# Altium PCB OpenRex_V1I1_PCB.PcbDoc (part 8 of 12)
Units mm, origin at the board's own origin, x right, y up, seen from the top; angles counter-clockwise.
Board outline 70 x 95 mm, 10 copper layers (L1, L2, L3, L4 (PWR), L5 (PWR), L6 (PWR), L7 (PWR), L8, L9, L10), stack 1.632 mm thick; 1080 components, 708 nets, 3831 pads, 2373 vias.
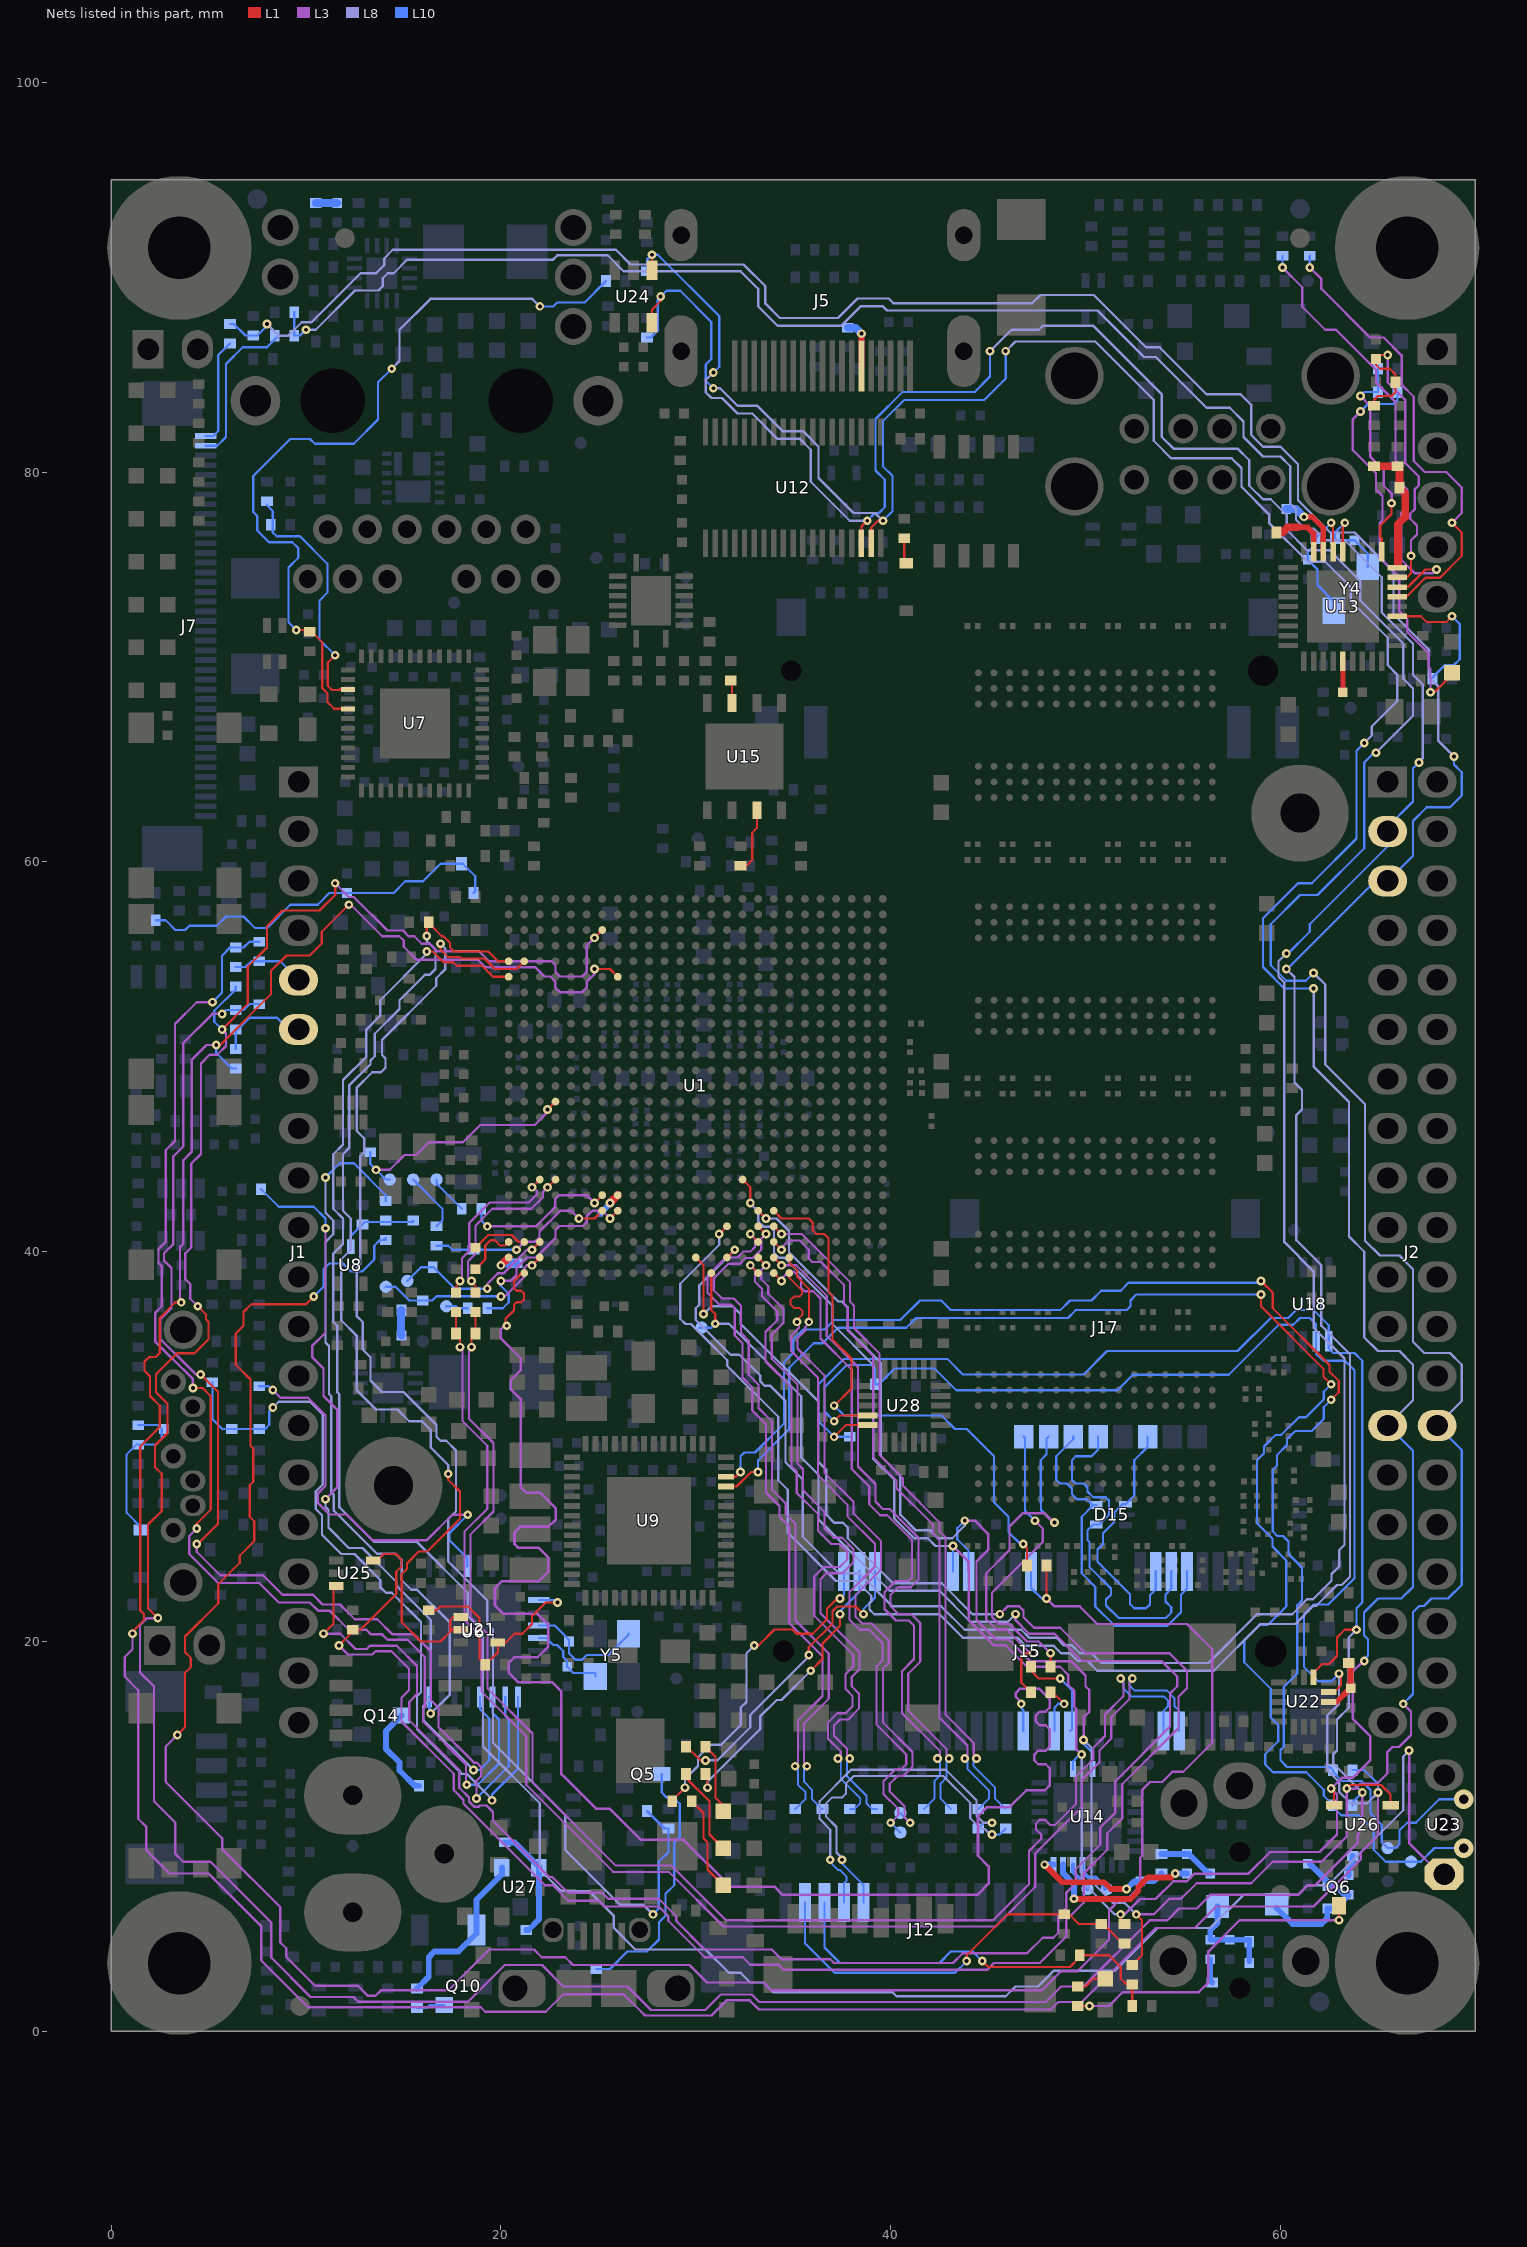
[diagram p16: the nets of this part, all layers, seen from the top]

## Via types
v1: diameter 0.45, hole 0.2, L1 to L10, tented both sides, 2369 vias
v2: diameter 1, hole 0.5, L1 to L10, tented top, 4 vias

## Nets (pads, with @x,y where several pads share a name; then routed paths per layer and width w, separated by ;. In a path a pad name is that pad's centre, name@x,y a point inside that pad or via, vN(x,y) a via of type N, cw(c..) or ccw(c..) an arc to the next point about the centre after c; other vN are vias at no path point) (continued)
HP_OUT_L: C285.1 C289.1 C290.2 FB22.1 R231.2 | length 5
  L10 w0.3: C290.2@56.775,6.4 56.775,5.575 56.4,5.2 C285.1@56.4,4.7 C289.1@57.4,4.7 58.4,4.7 FB22.1@58.4,3.6
HP_OUT_R: C284.1 C288.1 C291.2 FB21.1 R230.2 | length 7.7
  L10 w0.3: C291.2@59.8,6.325 60.625,5.5 62.1,5.5 62.4,5.8 C288.1@62.4,6.3 62.8,6.3 C284.1@63.5,7 63.3,7 62.8,7.5 62.5,7.5 62.5,7.6 FB21.1@61.5,8.6
HUB_CFG_SEL0: R221.2 U13.24 | length 24.3
  L1 w0.114: U13.24@66,73.6 66.462,73.6 67.442,74.58 68.18,74.58 69.3,75.7 69.3,76.9 v1(68.8,77.4)
  L3 w0.12: v1(61.5,90.5) 62.1,89.9 62.1,89.4 64.6,86.9 65.3,86.9 66.215,85.985 66.215,84.485 66.84,83.86 66.84,80.56 67.4,80 68.5,80 69.3,79.2 69.3,77.9 v1(68.8,77.4)
  L10 w0.114: v1(61.5,90.5) R221.2@61.5,91.1
HUB_CFG_SEL1: R220.2 U13.25 | length 23.2
  L1 w0.114: U13.25@66,74.1 66.544,74.1 67.444,75 v1(68,75)
  L3 w0.12: v1(60.1,90.5) 61.115,89.485 61.115,88.485 62.3,87.3 62.844,87.3 64.9,85.244 64.9,84.6 65.9,83.6 65.9,80.6 66.1,80.4 66.1,79.5 66.5,79.1 66.5,78.2 66.2,77.9 66.2,75.5 66.9,74.8 67.8,74.8 v1(68,75)
  L10 w0.114: v1(60.1,90.5) R220.2@60.1,91.1
HUB_CRFILT: C254.1 U13.14 | length 1.6
  L1 w0.25: C254.1@63.2,68.7 U13.14@63.2,70.3
HUB_LED: D12.2 R219.1 | length 20.4
  L1 w0.114: v1(67.7,68.7) 67.9,68.7 68.8,69.6 D12.2@68.8,69.7
  L3 w0.12: v1(64.1,83.1) 63.715,82.715 63.715,81.12 64.9,79.935 64.9,79.1 65.235,78.765 65.235,77.535 65.1,77.4 65.1,75.6 66.1,74.6 66.1,72.86 66.5,72.46 66.5,71.8 67.6,70.7 67.6,70 67.7,69.9 v1(67.7,68.7)
  L10 w0.114: v1(64.1,83.1) 64.485,83.485 65.785,83.485 66,83.7 R219.1@66,84.1
HUB_NON_REM1: R224.2 U13.22 | length 7.3
  L1 w0.114: U13.22@66,72.6 67.2,72.6 67.5,72.3 68.5,72.3 v1(68.8,72.6)
  L10 w0.114: R224.2@67.8,69.4 67.8,69.456 68.444,70.1 68.9,70.1 69.2,70.4 69.2,72.2 v1(68.8,72.6)
HUB_PLLFILT: C253.1 U13.34 | length 3.5
  L1 w0.28: v1(61.2,77.7) 61.635,77.7 62.2,77.135 U13.34@62.2,75.9
  L10 w0.4: C253.1@60.3,78.1 60.8,78.1 v1(61.2,77.7)
HUB_RBIAS: R222.1 U13.35 | length 3.1
  L1 w0.28: 60.9,77.165 61.393,77.165 61.7,76.858 U13.35@61.7,75.9
  L1 w0.4: R222.1@59.8,76.9 60.1,76.9 60.365,77.165 60.9,77.165
HUB_RESETN: C416.1 R217.1 R218.1 U13.26 | length 17.8
  L1 w0.114: R217.1@64.8,83.4 64.8,83.7 65,83.9 65.7,83.9 65.9,84.1 R218.1@65.9,84.6 65.9,85 65.6,85.3 65.1,85.3 64.9,85.5 C416.1@64.9,85.8 65.1,86 v1(65.5,86) ; U13.26@66,74.6 66.5,74.6 66.7,74.8 v1(66.7,75.7)
  L3 w0.12: v1(65.5,86) 65.5,84.6 66.4,83.7 66.4,80.459 67.1,79.759 67.1,79.318 66.88,79.098 66.88,78.08 66.656,77.856 66.656,77.6 67,77.256 67,76.8 66.7,76.5 v1(66.7,75.7)
HUB_VBUS_DET: R169.1 R215.2 R216.1 U13.27 | length 6.7
  L1 w0.28: U13.27@66,75.1 U13.27@66,75.175
  L1 w0.4: R169.1@64.8,80.3 R215.2@66,80.3 66.1,80.2 R216.1@66.1,79.2 66.4,78.9 66.4,77.7 66.025,77.325 U13.27@66.025,75.175
HUB_XTALIN: C415.1 R358.2 U13.33 Y4.3 | length 7.1
  L1 w0.114: v1(62.6,77.4) 62.7,77.3 U13.33@62.7,75.9
  L10 w0.114: v1(62.6,77.4) R358.2@61.8,76.6 61.8,76.3 61.4,75.9 C415.1@61.4,75.5 61.9,75 61.9,74.2 62.725,73.375 Y4.3@62.725,72.875
HUB_XTALOUT: C242.1 R358.1 U13.32 Y4.1 | length 5.2
  L1 w0.114: U13.32@63.2,75.9 63.2,77.3 v1(63.3,77.4)
  L10 w0.114: v1(63.3,77.4) 62.8,76.9 R358.1@62.8,76.6 62.9,76.5 C242.1@63.8,76.5 64.475,75.825 Y4.1@64.475,75.125
I2C1_SCL: R132.1 R238.1 R278.1 U1.H20 U18.6 U22.4 U28.11 | length 218
  L1 w0.114: v1(1.1,20.4) 1.1,20.5 1.685,21.085 1.685,21.409 1.5,21.594 1.5,30 2.5,31 2.5,32.1 2,32.6 2,33.6 1.715,33.885 1.715,34.359 1.956,34.6 2.3,34.6 2.5,34.8 2.5,36.6 3.3,37.4 v1(3.6,37.4) ; v1(5.4,50.6) 5.6,50.6 8.2,53.2 8.2,54.4 9,55.2 10.2,55.2 10.815,55.815 10.815,56.415 v1(12.2,57.8) ; v1(24.8,54.5) 25.6,54.5 U1.H20@26,54.1 ; v1(37.1,31.3) 37.4,31.6 U28.11@38.825,31.6 ; U22.4@62.475,17.4 62.751,17.4 63.1,17.749 63.1,18.25 v1(63,18.35)
  L3 w0.12: v1(1.1,20.4) 1.1,19.6 0.7,19.2 0.7,18.2 1.4,17.5 1.4,10.9 1.8,10.5 1.8,9.3 3,8.1 5,8.1 7.7,5.4 7.7,3.644 10.109,1.235 18.965,1.235 19.2,1 22.3,1 23.2,1.9 26.3,1.9 27.2,1 27.39,0.81 30.8,0.81 31.575,1.585 32.775,1.585 33.245,1.115 48.215,1.115 48.6,1.5 49.8,1.5 53.6,5.3 55.6,5.3 56.7,6.4 61.7,6.4 64.115,8.815 64.115,9.171 65,10.056 v1(65,12.25) ; v1(3.6,37.4) 3.535,37.465 3.535,40.235 3.7,40.4 3.7,44.684 4.135,45.119 4.135,49.835 4.9,50.6 v1(5.4,50.6) ; v1(12.2,57.8) 12.3,57.8 13.915,56.185 14.789,56.185 15.015,55.959 15.015,55.641 15.671,54.985 18.815,54.985 19.2,54.6 21.756,54.6 22.241,54.115 22.529,54.115 22.785,53.859 22.785,53.571 23.041,53.315 24.159,53.315 24.415,53.571 24.415,53.859 24.8,54.244 v1(24.8,54.5)
  L8 w0.12: v1(63,18.35) 63,16.8 62.4,16.2 62.4,13.4 63.015,12.785 63.015,12.285 63.6,11.7 64.45,11.7 v1(65,12.25)
  L10 w0.114: v1(5.4,50.6) 5.4,50.2 6.2,49.4 R278.1@6.4,49.4 ; v1(37.1,31.3) 36.6,31.8 36.6,33.044 37.741,34.185 39.015,34.185 39.2,34 R132.1@39.2,33.2 39.4,33.2 40.2,34 42.256,34 43.371,32.885 51.635,32.885 52.435,33.685 57.341,33.685 59.906,36.25 60.65,36.25 61,36.6 61.5,36.6 61.825,36.275 U18.6@61.825,35.4 61.825,34.775 62.2,34.4 63.315,34.4 63.8,33.915 63.8,23.244 62.456,21.9 61.7,21.9 61.2,21.4 61.2,18.7 61.935,17.965 62.615,17.965 v1(63,18.35) ; R238.1@63.7,13.4 64.3,13.4 65,12.7 v1(65,12.25)
I2C1_SCL_CON: J1.6 R278.2 R279.2 | length 4.7
  L10 w0.114: R278.2@6.4,50.4 R279.2@6.4,51.4 6.5,51.4 7.1,52 8.52,52 9.12,51.4 J1.6@9.62,51.4
I2C1_SCL_MCU: R279.1 R291.1 U6.10 | length 62.3
  L1 w0.114: v1(4.4,25) 4.444,25 5.485,26.041 5.485,32.815 v1(4.6,33.7)
  L3 w0.12: v1(4.4,25) 4.4,24.6 5.6,23.4 7.8,23.4 8.8,22.4 10.356,22.4 10.856,21.9 11.74,21.9 12.5,21.14 13.66,21.14 14.435,20.365 15.535,20.365 16.415,19.485 16.415,16.985 16.8,16.6 16.8,15.6 18.615,13.785 18.759,13.785 18.985,13.559 18.985,13.085 18.75,12.85 v1(18.75,11.95) ; v1(4.6,33.7) 4.361,33.7 3.231,34.83 3.22,34.83 2.54,35.51 2.54,36.54 3.1,37.1 3.1,39.156 2.715,39.541 2.715,39.915 3.2,40.4 3.2,44.9 3.7,45.4 3.7,50.7 5.2,52.2 v1(5.7,52.2)
  L10 w0.114: v1(5.7,52.2) 5.9,52.4 R279.1@6.4,52.4 6.8,52.4 7.1,52.7 R291.1@7.6,52.7 ; v1(18.75,11.95) 20.4,13.6 20.4,16 20.225,16.175 U6.10@20.225,17.15
I2C1_SCL_PMIC: R238.2 TP18.1 U9.54 | length 78.2
  L1 w0.114: U9.54@31.55,28.45 32.05,28.45 v1(32.3,28.7) ; v1(59,38.5) 59.6,37.9 59.6,37.1 62.515,34.185 62.515,33.841 62.985,33.371 62.985,32.785 v1(62.6,32.4)
  L1 w0.4: v2@69.35,11.95 v2(69.4,11.9)
  L10 w0.114: v1(32.3,28.7) 32.3,29.5 32.5,29.7 33.044,29.7 34.52,31.176 34.52,34.32 35,34.8 35,35.5 35.5,36 36.6,36 37.1,36.5 40.5,36.5 41.5,37.5 42.6,37.5 43.1,37 48.7,37 49.2,37.5 50.3,37.5 50.8,38 51.8,38 52.2,38.4 58.9,38.4 v1(59,38.5) ; v1(62.6,32.4) 62.215,32.015 62.215,31.415 61.6,30.8 60.756,30.8 60.335,30.38 60.335,30.08 59.815,29.559 59.815,29.241 59.815,29.015 59.598,28.798 59.598,25.658 59.841,25.415 60.129,25.415 60.415,25.129 60.415,24.485 61.1,23.8 61.1,22.1 60.86,21.86 60.86,18.36 60.165,17.665 60.165,14.6 60,14.435 60,13.9 60.335,13.565 62.535,13.565 R238.2@62.7,13.4 62.7,13.3 63.165,12.835 64.165,12.835 64.615,12.385 64.615,11.185 65.2,10.6 65.2,9.7 TP18.1@65.5,9.4 65.9,9.4 66.1,9.6 66.1,10.3 66.5,10.7 66.942,10.7 68.142,11.9 v2(69.4,11.9)
I2C1_SDA: R28.1 R247.1 R276.1 U1.G23 U18.5 U22.6 U28.12 | length 218.7
  L1 w0.114: v1(2.4,21.2) 1.9,21.7 1.9,26 2.6,26.7 2.6,28.6 2.258,28.942 2.258,30.058 2.9,30.7 2.9,32.2 2.3,32.8 2.3,33.7 3.385,34.785 4.285,34.785 5,35.5 5,36.406 4.865,36.541 4.865,36.785 v1(4.45,37.2) ; v1(5.7,51.4) 7.015,52.715 7.015,54.615 8,55.6 8,56.7 8.8,57.5 10.7,57.5 11.5,58.3 v1(11.5,58.9) ; v1(24.8,56.1) U1.G23@25.2,56.5 ; v1(37.1,30.5) 37.7,31.1 U28.12@38.825,31.1 ; U22.6@61.7,18.175 61.7,18.4 62.144,18.844 62.494,18.844 62.9,19.25 62.9,20.2 63.3,20.6 v1(63.9,20.6)
  L3 w0.12: v1(2.4,21.2) 1.844,21.2 1.485,20.841 1.485,18.415 2.2,17.7 2.2,11.8 3.3,10.7 3.3,9.1 3.7,8.7 5.1,8.7 8.215,5.585 8.215,3.781 10.24,1.756 12.444,1.756 12.685,1.515 18.315,1.515 20.2,3.4 22.104,3.4 23.204,2.3 26.5,2.3 27.71,1.09 30.49,1.09 31.285,1.885 32.871,1.885 33.256,1.5 47.956,1.5 48.756,2.3 49.9,2.3 53.3,5.7 54.2,5.7 54.8,6.3 55.7,6.3 56.4,7 60.9,7 61.4,7.5 61.8,7.5 63.956,9.656 63.956,10.1 64.2,10.344 v1(64.2,12.25) ; v1(4.45,37.2) 4.065,37.585 4.065,38.335 3.815,38.585 3.815,39.915 4.12,40.22 4.12,44.52 4.615,45.015 4.615,49.659 5.056,50.1 5.444,50.1 5.9,50.556 5.9,51.2 v1(5.7,51.4) ; v1(11.5,58.9) 12.2,58.2 12.456,58.2 14.181,56.475 14.975,56.475 15.265,56.185 15.559,56.185 15.944,55.8 16.344,55.8 16.729,55.415 18.885,55.415 19.4,54.9 22.6,54.9 22.8,54.7 22.8,54.356 23.041,54.115 24.159,54.115 24.4,54.356 24.4,55.7 v1(24.8,56.1)
  L8 w0.12: v1(63.9,20.6) 63.5,20.2 63.5,16.6 62.9,16 62.9,14.4 62.7,14.2 62.7,13.75 v1(64.2,12.25)
  L10 w0.114: v1(5.7,51.4) 5.3,51.8 5.3,52.356 6.4,53.456 R276.1@6.4,53.6 ; R28.1@37.9,30.5 v1(37.1,30.5) 36.3,31.3 36.3,33.2 37.6,34.5 42.9,34.5 43.7,33.7 49.9,33.7 51.1,34.9 57.8,34.9 59.5,36.6 60.4,36.6 60.8,37 61.7,37 62.475,36.225 U18.5@62.475,35.4 62.475,35.025 62.7,34.8 63.8,34.8 64.2,34.4 64.2,22 63.9,21.7 v1(63.9,20.6) ; R247.1@63.7,11.6 63.7,11.75 v1(64.2,12.25)
I2C1_SDA_CON: J1.5 R276.2 R277.2 | length 3.8
  L10 w0.114: R276.2@6.4,54.6 6.9,54.6 7.2,54.9 R277.2@7.6,54.9 8.68,54.9 9.62,53.96 J1.5@9.62,53.94
I2C1_SDA_MCU: R277.1 R290.1 U6.11 | length 64.5
  L1 w0.114: v1(4.2,33) 4.7,33 5.12,32.58 5.12,26.764 4.4,26.044 v1(4.4,25.8)
  L3 w0.12: v1(4.2,33) 4.2,33.466 3.116,34.55 3.104,34.55 2.26,35.394 2.26,36.86 2.6,37.2 2.6,39.26 2.435,39.425 2.435,40.135 2.8,40.5 2.8,45.2 3.285,45.685 3.285,51.685 4.4,52.8 v1(5.2,52.8) ; v1(4.4,25.8) 4.015,25.415 4.015,24.485 5.5,23 7.6,23 8.6,22 10.2,22 10.615,21.585 11.215,21.585 12.2,20.6 13.106,20.6 13.341,20.365 13.907,20.365 14.187,20.085 15.215,20.085 16.1,19.2 16.1,16.629 16.015,16.544 16.015,15.885 18.215,13.685 18.215,12.685 v1(18.25,12.65) ; v1@18.3,12.7 v1@18.4,12.6
  L10 w0.114: v1(5.2,52.8) 5.7,53.3 5.7,55.2 6.1,55.6 R290.1@6.4,55.6 6.8,55.6 7.1,55.9 R277.1@7.6,55.9 ; v1(18.25,12.65) 18.815,12.65 19.9,13.735 19.9,16 19.575,16.325 U6.11@19.575,17.15
I2C1_SDA_PMIC: R247.2 TP21.1 U9.53 | length 77.7
  L1 w0.114: U9.53@31.55,27.95 32.094,27.95 32.844,28.7 v1(33.2,28.7) ; v1(59,37.8) 59,37.2 62.2,34 62.2,33.6 v1(62.6,33.2)
  L1 w0.4: v2@69.35,9.45 v2@69.4,9.4
  L10 w0.114: v1(33.2,28.7) 33.2,29.3 34.8,30.9 34.8,34.044 36.056,35.3 36.5,35.3 37.3,36.1 40.8,36.1 41.3,36.6 49.1,36.6 49.5,37 52.1,37 52.3,37.2 52.3,37.5 52.6,37.8 v1(59,37.8) ; v1(62.6,33.2) 62.215,32.815 62.215,32.411 61.304,31.5 60.944,31.5 60.044,30.6 59.756,30.6 59.157,30.002 59.157,29.657 58.8,29.3 58.8,26.06 59.585,25.275 59.585,24.871 60.3,24.156 60.3,21.8 59.36,20.86 58.937,20.86 58.14,20.063 58.14,18.937 59.5,17.577 59.5,16.1 59.885,15.715 59.885,14.885 59.215,14.215 59.215,13.685 59.615,13.285 61.321,13.285 62.215,12.391 62.215,12.085 R247.2@62.7,11.6 62.7,11.5 63.115,11.085 64.015,11.085 64.785,10.315 64.785,9.315 65.4,8.7 TP21.1@66.7,8.7 67.2,8.7 67.9,9.4 v2@69.4,9.4
  other v2: 69.4,9.39
I2C2_CSI_SCL: J12.13 R53.1 R154.2 R191.2 | length 21.4
  L1 w0.114: v1(44.7,3.6) 45,3.3 49.2,3.3 49.7,3.8 R53.1@49.7,3.9 51.2,3.9 51.8,3.3 51.8,2.7 52.1,2.4 R154.2@52.4,2.4 R191.2@52.4,1.3
  L10 w0.114: J12.13@36.6,6.6 36.6,4.3 37.4,3.5 42.5,3.5 43.1,4.1 44.2,4.1 v1(44.7,3.6)
I2C2_CSI_SDA: J12.14 R52.1 R54.2 R156.2 | length 21.1
  L1 w0.114: v1(43.9,3.6) 43.9,3.9 46,6 R52.1@48.9,6 49.156,6 49.656,5.5 R54.2@50.8,5.5 50.9,5.5 51.9,4.5 R156.2@52,4.5
  L10 w0.114: J12.14@35.6,6.6 35.6,4.52 37.12,3 43.3,3 v1(43.9,3.6)
I2C2_SCL: J2.28 J15.30 R134.1 R154.1 U1.U5 U12.17 U14.29 U24.1 U26.6 | length 220
  L1 w0.114: U24.1@27.75,90.45 v1(27.75,91.15) ; U1.U5@33.2,42.1 v1(33.6,41.7) ; U12.17@38.5,76.35 38.5,77.2 v1(38.8,77.5) ; R154.1@52.4,3.4 52.9,3.9 52.9,5.7 v1(52.6,6) ; v1(63.4,12.45) 63.585,12.635 65.159,12.635 65.65,12.144 U26.6@65.65,11.6
  L3 w0.12: v1(43.8,26.2) 44.319,26.2 45,25.519 45,24.7 44.4,24.1 44.4,21.1 45.4,20.1 46.056,20.1 47.176,18.98 49.275,18.98 50,18.255 50,17.7 50.185,17.515 50.185,16.385 49.9,16.1 v1(49.9,14.95) ; v1(52.6,6) 53.5,6 54.3,6.8 54.9,6.8 55.7,7.6 58.5,7.6 59.6,8.7 62.1,8.7 63.4,10 v1(63.4,12.45) 63.85,12.45 64.1,12.7 64.944,12.7 65.485,13.241 65.485,14.329 65.741,14.585 66.085,14.585 66.7,15.2 66.7,16.4 v1(66.3,16.8)
  L8 w0.12: v1(30.9,85.1) 30.515,84.715 30.515,84.085 30.8,83.8 31.344,83.8 32.144,83 32.9,83 34.2,81.7 35.344,81.7 35.9,81.144 35.9,79.5 37.9,77.5 v1(38.8,77.5) ; v1(33.6,41.7) 34.144,41.7 34.785,41.059 34.785,39.971 37.311,37.444 37.5,37.444 37.8,37.144 37.8,36 39.5,34.3 39.5,29.5 40.5,28.5 40.5,26.5 41.3,25.7 42.025,25.7 42.425,25.3 43.156,25.3 43.8,25.944 v1(43.8,26.2) ; v1(45.1,86.2) 46.2,87.3 47.6,87.3 47.8,87.5 50.4,87.5 53.9,84 53.9,81.81 54.51,81.2 57.8,81.2 58.4,80.6 58.4,79.3 59.1,78.6 59.5,78.6 60.32,77.78 60.32,77.036 61.366,75.99 62.51,75.99 64.1,74.4 64.1,73.4 66.3,71.2 66.3,69.4 66.8,68.9 66.8,67.5 v1(64.9,65.6) ; v1(49.9,14.95) 50.3,14.55 50.3,7.7 51.4,6.6 52,6.6 v1(52.6,6) ; v1(61.7,54.3) 62.3,53.7 62.3,49.6 64.34,47.56 64.34,40.56 65.1,39.8 66.1,39.8 66.8,39.1 66.8,35.38 67.38,34.8 68.7,34.8 69.3,34.2 69.3,32.34 J2.28@68.04,31.08
  L10 w0.114: R134.1@27.5,90.3 27.5,90.9 v1(27.75,91.15) 28.05,91.15 31.2,88 31.2,85.4 v1(30.9,85.1) ; v1(38.8,77.5) 39.2,77.9 39.4,77.9 39.7,78.2 39.7,79.6 39.22,80.08 39.22,82.72 40.6,84.1 44.3,84.1 45.1,84.9 v1(45.1,86.2) ; v1(43.8,26.2) 43.412,25.813 43.412,25.243 44,24.656 J15.30@44,23.6 ; v1(49.9,14.95) 49.9,14.744 50.33,14.314 50.33,13.47 U14.29@50.35,13.45 ; v1(61.7,54.3) 61.3,53.9 60.3,53.9 59.5,54.7 59.5,56.8 61,58.3 61.9,58.3 64.3,60.7 64.3,65.1 64.8,65.6 v1(64.9,65.6) ; v1(66.3,16.8) 66.8,17.3 66.8,21.5 67.115,21.815 67.359,21.815 67.744,22.2 68.6,22.2 69.3,22.9 69.3,29.82 J2.28@68.04,31.08
I2C2_SDA: J2.27 J15.32 R133.1 R156.1 U1.T7 U12.18 U14.27 U24.6 U26.1 | length 208.2
  L1 w0.114: U24.6@27.75,87.65 27.75,88.331 28.2,88.781 v1(28.2,89) ; U1.T7@32.4,43.7 32.8,43.3 v1(32.8,42.5) ; U12.18@39,76.35 39,77.156 39.344,77.5 v1(39.6,77.5) ; v1(51.8,6) 51.8,5.7 R156.1@52,5.5 ; v1(62.6,12.45) 62.75,12.3 U26.1@62.75,11.6
  L3 w0.12: v1(43.2,24.9) 44,24.1 44,21.1 45.3,19.8 45.9,19.8 47,18.7 48.7,18.7 49.115,18.285 49.115,17.785 49.415,17.485 49.415,16.641 49.515,16.541 49.515,14.485 v1(49.8,14.2) ; v1(51.8,6) 52,6 52.785,6.785 53.589,6.785 54.504,7.7 55.2,7.7 55.59,8.09 58.36,8.09 59.47,9.2 62,9.2 62.9,10.1 62.9,12.15 v1(62.6,12.45) 63.15,13 63.7,13 64.6,13.9 64.6,15.144 63.7,16.044 63.7,18.444 ; v1(64.3,19) 64.256,19 63.7,18.444 ; v1@64.3,19.05 63.7,18.45 63.7,18.444
  L8 w0.12: v1(30.9,84.3) 31.244,84.3 32.149,83.395 33.161,83.395 34.456,82.1 35.5,82.1 36.3,81.3 36.3,79.7 38.1,77.9 39.2,77.9 v1(39.6,77.5) ; v1(32.8,42.5) 32.8,42.47 33.2,42.07 33.2,41.556 33.471,41.285 33.815,41.285 34.015,41.085 34.015,39.941 34.271,39.685 34.559,39.685 37,37.244 37,36.3 39.1,34.2 39.1,29.392 40.185,28.307 40.185,26.315 41.2,25.3 41.9,25.3 42.3,24.9 v1(43.2,24.9) ; v1(45.9,86.2) 46.4,86.7 50.5,86.7 53.5,83.7 53.5,81.6 54.4,80.7 57.5,80.7 58,80.2 58,79.24 59.415,77.825 59.415,77.391 61.406,75.4 62.3,75.4 63.6,74.1 63.6,73.4 65.5,71.5 65.5,70.1 65.985,69.615 65.985,68.241 64.685,66.941 64.685,66.485 v1(64.3,66.1) ; v1(49.8,14.2) 49.8,7.7 51.5,6 v1(51.8,6) ; v1(61.7,53.5) 61.7,49.5 63.515,47.685 63.515,40.785 64.3,40 64.3,35.6 65,34.9 66.1,34.9 66.8,34.2 66.8,32.38 J2.27@65.5,31.08
  L10 w0.114: R133.1@27.5,86.9 27.7,86.9 28.05,87.25 28.05,88.85 v1(28.2,89) 28.5,89.3 29.2,89.3 30.8,87.7 30.8,85.8 30.515,85.515 30.515,84.685 v1(30.9,84.3) ; v1(39.6,77.5) 40.1,78 40.1,79.8 39.6,80.3 39.6,82.6 40.7,83.7 44.8,83.7 45.9,84.8 v1(45.9,86.2) ; J15.32@43.2,23.6 v1(43.2,24.9) ; U14.27@49.35,13.45 49.35,13.85 49.7,14.2 v1(49.8,14.2) ; v1(61.7,53.5) 60.2,53.5 59.1,54.6 59.1,57.1 60.9,58.9 61.6,58.9 63.9,61.2 63.9,65.7 v1(64.3,66.1) ; v1@64.3,19.1 64.485,19.285 64.485,20.115 64.285,20.315 64.285,21.485 65,22.2 66.2,22.2 66.8,22.8 66.8,29.78 J2.27@65.5,31.08
I2C3_CSI1_SCL: J7.40 R196.1 | length 5.5
  L10 w0.114: J7.40@4.85,81.85 5.25,81.85 5.5,82.1 5.5,86 R196.1@6.1,86.6
I2C3_CSI1_SDA: J7.39 R195.1 | length 8.1
  L10 w0.114: J7.39@4.85,81.35 5.45,81.35 5.9,81.8 5.9,85.544 6.756,86.4 8,86.4 R195.1@8.5,86.9
I2C3_SCL: J2.5 R142.1 R196.2 U1.R4 | length 186
  L1 w0.114: v1(31.2,40.9) U1.R4@31.6,41.3
  L8 w0.12: v1(8,87.6) 8.6,87 9.1,87 9.785,87.685 10.285,87.685 12.8,90.2 13.6,90.2 14.015,90.615 14.015,90.959 14.455,91.399 25.906,91.399 26.656,90.65 32.45,90.65 33.571,89.529 33.571,88.641 34.311,87.9 37.3,87.9 38.3,88.9 39.9,88.9 40.135,88.665 47.265,88.665 47.685,89.085 50.415,89.085 53.1,86.4 53.8,86.4 56.215,83.985 57.959,83.985 58.5,83.444 58.5,81.9 59.1,81.3 60,81.3 60.9,80.4 60.9,78.556 62.556,76.9 63.8,76.9 65.8,74.9 65.8,72.7 67.615,70.885 67.615,69.485 68.1,69 68.1,66.2 v1(68.9,65.4) ; v1(31.2,40.9) 31.2,40.356 29.2,38.356 29.2,36.556 29.471,36.285 29.759,36.285 30.6,35.444 31.615,34.429 31.615,34.141 34.23,31.526 34.23,28.27 34.715,27.785 34.715,25.585 37.2,23.1 38.244,23.1 39,22.344 39,22.056 38.915,21.971 38.915,21.641 39.156,21.4 42.5,21.4 43.7,20.2 46.5,20.2 46.915,19.785 47.2,19.785 48.359,19.785 48.744,19.4 49.2,19.4 49.6,19 50.1,19 50.6,18.5 56.577,18.5 58.977,20.9 60.764,20.9 61.7,21.836 61.836,21.836 62.9,22.9 63.144,22.9 63.565,23.321 63.565,34.735 62.1,36.2 62.1,39.3 60.815,40.585 60.815,47.015 61.1,47.3 61.1,48.3 60.715,48.685 60.715,54.085 v1(60.3,54.5)
  L10 w0.114: R196.2@6.1,87.6 6.3,87.6 6.9,87 R142.1@7.3,87 7.5,87 8,87.5 v1(8,87.6) ; v1(60.3,54.5) 60.344,54.5 64.864,59.02 J2.5@65.5,59.02 66.8,60.32 66.8,62.1 67.5,62.8 68.7,62.8 69.3,63.4 69.3,64.6 68.9,65 v1(68.9,65.4)
I2C3_SDA: J2.3 R137.1 R195.2 U1.R2 | length 176.6
  L1 w0.114: U1.R2@31.6,39.7 v1(32,40.1)
  L8 w0.12: v1(10,87.3) 10.5,87.3 12.515,89.315 13.715,89.315 13.941,89.541 13.941,89.941 14.2,90.2 14.5,90.2 15.2,90.9 22.681,90.9 22.9,91.119 25.481,91.119 26.3,90.3 32.3,90.3 33.2,89.4 33.2,88.504 34.204,87.5 37.456,87.5 38.456,88.5 39.6,88.5 39.815,88.285 50.615,88.285 53,85.9 53.6,85.9 56.2,83.3 57.4,83.3 58.1,82.6 58.1,81.8 59.1,80.8 60,80.8 60.5,80.3 60.5,78.4 60.8,78.1 60.8,77.556 61.271,77.085 61.715,77.085 62.3,76.5 63.3,76.5 65.2,74.6 65.2,72.79 66.8,71.19 66.8,69.6 67.3,69.1 67.3,65.3 v1(67.1,65.1) ; v1(32,40.1) 32,40.09 30.185,38.275 30.185,37.285 30,37.1 30,36.5 31.785,34.715 32.229,34.715 33.315,33.629 33.315,33.341 33.541,33.115 33.829,33.115 34.6,32.344 34.6,29.2 35.485,28.315 35.485,25.371 37.356,23.5 38.4,23.5 40.1,21.8 42.6,21.8 43.8,20.6 46.7,20.6 47.1,20.2 48.5,20.2 48.9,19.8 49.3,19.8 49.7,19.4 50.3,19.4 50.8,18.9 56.3,18.9 58.8,21.4 60.6,21.4 61.366,22.166 61.666,22.166 62.615,23.115 62.615,23.459 63.01,23.854 63.01,24.69 63.285,24.965 63.285,34.515 61.7,36.1 61.7,38.989 60.2,40.489 60.2,53.8 59.9,54.1 59.9,54.9 v1(60.3,55.3)
  L10 w0.114: R137.1@9.4,88.2 R195.2@9.4,87 9.7,87 v1(10,87.3) ; v1(60.3,55.3) 60.385,55.3 61.5,56.415 61.5,56.8 65.5,60.8 J2.3@65.5,61.56 65.5,61.8 66.8,63.1 66.8,64.8 v1(67.1,65.1)
IR_RCV: U1.A20 U23.1 | length 121.6
  L1 w0.114: v1(16.2,55.4) 16.5,55.4 17.055,54.845 17.555,54.845 17.732,54.668 19.032,54.668 19.6,54.1 U1.A20@20.4,54.1
  L3 w0.12: v1(66.6,14.4) 66.6,9.656 68.196,8.06 U23.1@68.4,8.06
  L8 w0.12: v1(16.2,55.4) 16.2,55.29 13.81,52.9 13.81,52.11 13.1,51.4 13.1,50.004 11.9,48.804 11.9,45.5 11.4,45 11.4,42.2 11.9,41.7 11.9,40.4 11.4,39.9 11.4,36.4 11.6,36.2 11.6,32.8 11.715,32.685 11.715,26.885 13.5,25.1 15.7,25.1 18.3,22.5 18.3,21.3 19.085,20.515 19.085,14.615 22,11.7 22,8.3 23.1,7.2 24.519,7.2 25.8,5.919 25.8,5.3 26.9,4.2 30.5,4.2 31.7,3 32.3,3 32.8,2.5 33.475,2.5 33.975,2 40.1,2 40.3,1.8 45.9,1.8 46.4,2.3 47.56,2.3 48.36,3.1 51.5,3.1 53.7,5.3 56.4,5.3 58.1,7 60.9,7 61.4,7.5 62.456,7.5 66.3,11.344 66.3,14.1 v1(66.6,14.4)
JTAG_MOD: R61.2 U1.H6 | length 1.3
  L1 w0.4: v1(25.6,42.5) U1.H6@26,42.9
  L10 w0.3: R61.2@25.1,41.965 25.6,42.465 v1(25.6,42.5)
JTAG_NTRST: R62.1 TP1.1 U1.C2 | length 9.4
  L1 w0.114: v1(21.6,39.3) U1.C2@22,39.7
  L3 w0.12: v1(20,37.7) 20.2,37.7 21.2,38.7 21.2,39.164 21.336,39.3 v1(21.6,39.3)
  L10 w0.114: TP1.1@14.1,38.2 14.6,38.2 15.3,37.5 R62.1@16,37.5 16.485,37.5 16.7,37.715 19.985,37.715 v1(20,37.7)
JTAG_TCK: R92.2 TP12.1 | length 1.1
  L10 w0.114: TP12.1@17.2,37.2 17.7,37.2 17.8,37.1 R92.2@18.3,37.1
JTAG_TCK_R: R92.1 U1.H5 | length 10.9
  L1 w0.114: v1(25.6,41.7) U1.H5@26,42.1
  L3 w0.12: v1(20,38.5) 20.5,38.5 20.8,38.8 20.8,39.16 21.34,39.7 21.8,39.7 22.8,40.7 22.8,41.1 23.015,41.315 24.2,41.315 24.4,41.515 24.4,41.8 24.7,42.1 25.2,42.1 v1(25.6,41.7)
  L10 w0.114: R92.1@19.3,37.1 20.1,37.1 20.4,37.4 20.4,37.844 20,38.244 v1(20,38.5)
JTAG_TDI: R90.2 TP2.1 | length 3.1
  L10 w0.114: TP2.1@15.5,43.7 17,42.2 17,41.6 R90.2@16.7,41.3
JTAG_TDI_R: R63.1 R90.1 U1.G5 | length 9.9
  L1 w0.114: v1(24,41.7) 24.8,41.7 U1.G5@25.2,42.1
  L3 w0.12: v1(20.8,40.1) 21.215,40.515 21.759,40.515 21.985,40.741 21.985,41.029 23.056,42.1 23.6,42.1 v1(24,41.7)
  L10 w0.114: R90.1@16.7,40.3 17.3,40.3 17.5,40.1 R63.1@18.6,40.1 v1(20.8,40.1)
JTAG_TDO: R161.2 TP13.1 | length 2
  L10 w0.114: TP13.1@16.7,43.7 16.7,43.5 17,43.2 R161.2@18,42.2
JTAG_TDO_R: R161.1 U1.G6 | length 8.2
  L1 w0.114: v1(24.8,42.5) U1.G6@25.2,42.9
  L3 w0.12: v1(19.3,41.3) 21.8,41.3 22.5,42 22.785,42.285 22.785,42.685 23,42.9 24.4,42.9 v1(24.8,42.5)
  L10 w0.114: R161.1@19,42.2 19,41.6 v1(19.3,41.3)
JTAG_TMS: R64.1 TP5.1 U1.C3 | length 8.7
  L1 w0.114: v1(21.6,40.1) U1.C3@22,40.5
  L3 w0.12: v1(19.3,38.1) 19.3,38.344 19.841,38.885 20.129,38.885 20.959,39.715 21.344,40.1 v1(21.6,40.1)
  L10 w0.114: TP5.1@15.2,38.5 15.9,39.2 R64.1@16.5,39.2 16.544,39.2 17.644,38.1 v1(19.3,38.1)
LED1: R82.1 R94.1 U7.17 | length 40.7
  L1 w0.114: v1(9.5,71.9) 10.1,71.9 R94.1@10.2,71.8 10.3,71.8 10.835,71.265 10.835,68.925 11.1,68.66 11.1,68.2 11.45,67.85 U7.17@12.16,67.85
  L8 w0.12: v1(14.4,85.3) 14.8,85.7 14.8,87.3 16.385,88.885 21.615,88.885 v1(22,88.5)
  L10 w0.114: v1(9.5,71.9) 9.1,72.3 9.1,75.1 9.6,75.6 9.6,76.1 9.3,76.4 8.1,76.4 7.5,77 7.5,77.744 7.3,77.944 7.3,79.8 9.2,81.7 10.206,81.7 10.459,81.447 12.447,81.447 13.7,82.7 13.7,84.6 v1(14.4,85.3) ; v1(22,88.5) 22.7,88.5 22.9,88.7 24.3,88.7 R82.1@25.4,89.8
LED2: R81.1 R102.2 U7.15 | length 13.1
  L1 w0.114: v1(11.5,70.6) 11.115,70.215 11.115,69.041 11.341,68.815 11.7,68.815 11.735,68.85 U7.15@12.16,68.85
  L10 w0.114: R81.1@8,78.3 8.3,78 8.3,76.9 8.5,76.7 9.7,76.7 11.1,75.3 11.1,73.8 10.7,73.4 10.7,71.4 v1(11.5,70.6)
LED_MPCIE_WLAN: J15.44 R268.1 | length 15.2
  L1 w0.114: R268.1@30.5,13.2 30.6,13.1 v1(30.6,12.5) ; v1(35.9,18.5) 36.5,19.1 36.5,19.9 37.4,20.8 v1(37.4,21.4)
  L8 w0.12: v1(30.6,12.5) 30.6,12.8 33.3,15.5 33.3,16.144 34.156,17 34.4,17 v1(35.9,18.5)
  L10 w0.114: v1(37.4,21.4) 37.4,21.544 38.4,22.544 J15.44@38.4,23.6
LED_MPCIE_WPAN: J15.46 R269.1 | length 17.4
  L1 w0.114: R269.1@28.8,11.8 28.8,11.85 v1(29.45,12.5) ; v1(33,19.8) 33.23,19.8 34.04,20.61 34.96,20.61 35.17,20.4 36,20.4 36.735,21.135 36.735,21.675 37.26,22.2 v1(37.4,22.2)
  L8 w0.12: v1(29.45,12.5) 29.45,12.95 30.115,13.615 30.115,14.059 30.756,14.7 31.3,14.7 32.3,15.7 32.3,16.6 32.6,16.9 32.6,19.4 v1(33,19.8)
  L10 w0.114: v1(37.4,22.2) 37.6,22.4 J15.46@37.6,23.6
LED_MPCIE_WWAN: J15.42 R267.1 | length 16.3
  L1 w0.114: R267.1@29.5,14.6 29.544,14.6 30.244,13.9 v1(30.5,13.9) ; v1(35.8,19.3) 35.8,19.7 37.015,20.915 37.015,21.559 37.256,21.8 38.2,21.8 v1(38.6,21.4)
  L8 w0.12: v1(30.5,13.9) 31.1,13.9 32.8,15.6 32.8,16.23 35.8,19.23 v1(35.8,19.3)
  L10 w0.114: v1(38.6,21.4) 38.6,21.656 39.2,22.256 J15.42@39.2,23.6
"LOCAL_PWR / NON_REM0": R219.2 R223.2 U13.28 | length 11.1
  L1 w0.114: U13.28@65.2,75.9 65.2,76.6 65.115,76.685 65.115,77.259 65.7,77.844 v1(65.7,78.4)
  L3 w0.12: v1(64.1,83.9) 64.6,83.4 64.6,80.8 65.3,80.1 65.3,79.3 65.7,78.9 v1(65.7,78.4)
  L10 w0.114: v1(64.1,83.9) 64.3,84.1 R219.2@65,84.1 R223.2@65,85.3
LVDS0_CLK_N: R135.1 U1.V4 | length 35.6
  L1 w0.1: U1.V4@34,41.3 v1(34.4,40.9)
  L3 w0.11: v1(34.4,40.9) 35.453,40.9 37.92,38.433 37.92,37.433 38.12,37.233 38.12,36.08 39.42,34.78 39.42,29.58 40.62,28.38 40.62,28 42.5,26.12 42.5,25.663 42.82,25.343 42.82,16.233 44.26,14.793 44.26,14.14 v1(44.4,14)
  L10 w0.1: v1(44.4,14) 44.26,13.86 44.26,13.6 45.36,12.5 45.36,11.94 R135.1@45.9,11.4
LVDS0_CLK_P: R138.1 U1.V3 | length 35.6
  L1 w0.1: U1.V3@34,40.5 v1(34.4,40.1)
  L3 w0.11: v1(34.4,40.1) 34.4,40.207 34.773,40.58 35.32,40.58 35.8,40.1 35.8,39.65 35.978,39.472 36.428,39.472 37.6,38.3 37.6,37.3 37.8,37.1 37.8,35.947 39.1,34.647 39.1,29.447 40.3,28.247 40.3,27.867 42.18,25.987 42.18,25.53 42.5,25.21 42.5,16.1 43.94,14.66 43.94,14.14 v1(43.8,14)
  L10 w0.1: v1(43.8,14) 43.94,13.86 43.94,13.467 45.04,12.367 45.04,11.94 R138.1@44.5,11.4
LVDS0_CLK_R_N: J12.11 R129.2 R135.2 | length 17.8
  L8 w0.11: v1(37.5,8.8) 37.5,8.893 37.22,9.173 37.22,10.48 36.675,11.025 36.675,11.675 37,12 37.515,12 37.7,12.185 37.7,12.7 38.1,13.1 42.7,13.1 44.08,11.72 44.08,10.927 44.627,10.38 44.827,10.38 45.107,10.1 v1(45.2,10.1)
  L10 w0.1: v1(37.5,8.8) 37.5,8.623 38.6,7.523 J12.11@38.6,6.6 ; v1(45.2,10.1) 45.6,10.1 R135.2@45.9,10.4
LVDS0_CLK_R_P: J12.12 R136.2 R138.2 | length 17.8
  L8 w0.11: v1(36.9,8.8) 36.9,10.347 36.355,10.892 36.355,11.808 37.967,13.42 42.833,13.42 44.4,11.853 44.4,11.06 44.76,10.7 v1(45.2,10.7)
  L10 w0.1: v1(36.9,8.8) 36.9,8.672 37.287,8.285 37.386,8.285 37.735,7.936 37.735,7.735 37.6,7.6 J12.12@37.6,6.6 ; R138.2@44.5,10.4 44.8,10.7 v1(45.2,10.7)
LVDS0_TX0_N: R65.1 U1.U2 | length 35.5
  L1 w0.1: U1.U2@33.2,39.7 v1(33.6,39.3)
  L3 w0.11: v1(33.6,39.3) 33.36,39.06 33.36,38.593 33.72,38.233 33.72,37.843 34.5,37.063 34.5,36.347 33.9,35.747 33.9,34.5 35.226,33.174 35.226,29.126 35.5,28.853 35.5,27.753 36.6,26.653 36.6,25.8 37.08,25.32 37.508,25.32 38.095,24.733 38.095,24.067 37.528,23.5 36.7,23.5 36.4,23.2 36.4,21.453 38.4,19.453 38.4,18.58 38,18.18 38,17.7 38.37,17.33 38.37,16.554 37.816,16 37.4,16 37.1,15.7 37.1,15.153 37.76,14.493 37.76,14.14 v1(37.9,14)
  L10 w0.1: v1(37.9,14) 37.76,13.86 37.76,13.093 38.76,12.093 38.76,11.7 39.06,11.4 R65.1@39.3,11.4
LVDS0_TX0_P: R119.1 U1.U1 | length 35.5
  L1 w0.1: v1(32.8,39.3) U1.U1@33.2,38.9
  L3 w0.11: v1(32.8,39.3) 33.04,39.06 33.04,38.46 33.4,38.1 33.4,37.71 34.18,36.93 34.18,36.48 33.58,35.88 33.58,34.367 34.906,33.041 34.906,28.994 35.18,28.72 35.18,27.62 36.28,26.52 36.28,25.667 36.947,25 37.375,25 37.775,24.6 37.775,24.2 37.395,23.82 36.567,23.82 36.08,23.333 36.08,21.32 38.08,19.32 38.08,18.713 37.68,18.313 37.68,17.567 38.05,17.197 38.05,16.687 37.683,16.32 37.267,16.32 36.78,15.833 36.78,15.02 37.44,14.36 37.44,14.14 v1(37.3,14)
  L10 w0.1: v1(37.3,14) 37.44,13.86 37.44,12.96 38.44,11.96 38.44,11.7 38.14,11.4 R119.1@37.9,11.4
LVDS0_TX1_N: R121.1 U1.U4 | length 35.6
  L1 w0.1: U1.U4@33.2,41.3 v1(33.6,40.9)
  L3 w0.11: v1(33.6,40.9) 33.36,40.66 33.36,40.107 32.933,39.68 32.57,39.68 32.27,39.38 31.68,39.38 30.925,38.625 30.925,38.028 31.353,37.6 31.953,37.6 32.32,37.233 32.32,35.833 32.72,35.433 32.72,33.68 33.22,33.18 33.22,31.98 33.92,31.28 33.92,27.78 34.62,27.08 34.62,26.533 35.12,26.033 35.12,21.08 36.82,19.38 36.82,17.067 35.56,15.807 35.56,13.74 v1(35.7,13.6)
  L10 w0.1: v1(35.7,13.6) 35.56,13.46 35.56,12.793 35.96,12.393 35.96,11.94 R121.1@36.5,11.4
LVDS0_TX1_P: R123.1 U1.U3 | length 35.6
  L1 w0.1: v1(32.8,40.9) U1.U3@33.2,40.5
  L3 w0.11: v1(32.8,40.9) 33.04,40.66 33.04,40.24 32.8,40 32.437,40 32.137,39.7 31.547,39.7 30.605,38.758 30.605,37.895 31.22,37.28 31.82,37.28 32,37.1 32,35.7 32.4,35.3 32.4,33.547 32.9,33.047 32.9,31.847 33.6,31.147 33.6,27.647 34.3,26.947 34.3,26.4 34.8,25.9 34.8,20.947 36.5,19.247 36.5,17.2 35.24,15.94 35.24,13.74 v1(35.1,13.6)
  L10 w0.1: R123.1@35.1,11.4 35.64,11.94 35.64,12.26 35.24,12.66 35.24,13.46 v1(35.1,13.6)
LVDS0_TX2_N: R126.1 U1.V2 | length 35.5
  L1 w0.1: U1.V2@34,39.7 v1(34.4,39.3)
  L3 w0.11: v1(34.4,39.3) 35.153,39.3 36.72,37.733 36.72,35.68 38.32,34.08 38.32,28.98 39.22,28.08 39.22,27.18 39.6,26.8 39.953,26.8 41.42,25.333 41.42,23.167 41.033,22.78 40.38,22.78 40,22.4 40,21.803 40.403,21.4 41.065,21.4 41.52,20.945 41.52,18.967 40.9,18.347 40.9,16.453 42.86,14.493 42.86,14.14 v1(43,14)
  L10 w0.1: v1(43,14) 42.86,13.86 42.86,13.007 42.56,12.707 42.56,11.94 R126.1@43.1,11.4
LVDS0_TX2_P: R128.1 U1.V1 | length 35.5
  L1 w0.1: U1.V1@34,38.9 v1(34.4,38.5)
  L3 w0.11: v1(34.4,38.5) 34.4,38.607 34.773,38.98 35.02,38.98 35.4,38.6 35.4,38.15 35.578,37.972 36.028,37.972 36.4,37.6 36.4,35.547 38,33.947 38,28.847 38.9,27.947 38.9,27.047 39.467,26.48 39.82,26.48 41.1,25.2 41.1,23.3 40.9,23.1 40.247,23.1 39.68,22.533 39.68,21.67 40.27,21.08 40.933,21.08 41.2,20.813 41.2,19.1 40.58,18.48 40.58,16.32 42.54,14.36 42.54,14.14 v1(42.4,14)
  L10 w0.1: R128.1@41.7,11.4 42.24,11.94 42.24,12.84 42.54,13.14 42.54,13.86 v1(42.4,14)
LVDS0_TX3_N: TP19.1 U1.W2 | length 35.5
  L1 w0.1: U1.W2@34.8,39.7 34.8,39.444 35.2,39.044 35.2,38.709 35.8,38.109 v1(35.8,36.4)
  L3 w0.11: v1(35.8,36.4) 35.8,36.307 35.62,36.127 35.62,35.957 35.22,35.557 35.22,35.033 36.6,33.653 36.6,28.653 38.1,27.153 38.1,26.553 39.512,25.141 39.512,23.712 38.2,22.4 38.2,21.263 38.543,20.92 39.033,20.92 39.9,20.053 39.9,18.9 39.6,18.6 39.6,15.853 41.12,14.333 41.12,13.567 40.653,13.1 40.353,13.1 39.95,12.697 39.95,12.303 40.71,11.543 40.71,10.99 v1(41,10.7)
  L10 w0.1: TP19.1@40.5,11.2 v1(41,10.7)
LVDS0_TX3_P: TP20.1 U1.W1 | length 35.5
  L1 w0.1: U1.W1@34.8,38.9 34.8,38.657 35.46,37.997 35.46,37.83 35.33,37.7 35.058,37.7 34.858,37.5 34.858,37.3 35.058,37.1 35.33,37.1 35.48,36.95 35.48,36.78 35.2,36.5 v1(35.2,36.4)
  L3 w0.11: v1(35.2,36.4) 35.3,36.3 35.3,36.09 34.9,35.69 34.9,34.9 36.28,33.52 36.28,28.52 37.78,27.02 37.78,26.42 39.192,25.008 39.192,23.845 37.88,22.533 37.88,21.13 38.41,20.6 38.9,20.6 39.58,19.92 39.58,19.033 39.28,18.733 39.28,15.72 40.8,14.2 40.8,13.7 40.52,13.42 40.22,13.42 39.63,12.83 39.63,12.17 40.39,11.41 40.39,11.09 v1(40,10.7)
  L10 w0.1: v1(40,10.7) TP20.1@40.5,10.2
MCU_BTN: C314.1 D35.1 R149.1 R390.2 | length 19.7
  L10 w0.114: R390.2@2.3,57 2.8,57 3.3,56.5 3.8,56.5 4.02,56.72 5.42,56.72 5.9,57.2 6.8,57.2 7.4,56.6 8,56.6 9.2,57.8 10.6,57.8 11.2,58.4 C314.1@12.1,58.4 14.5,58.4 15.1,59 16,59 16.9,59.9 D35.1@17.981,59.9 18.044,59.9 18.685,59.259 18.685,58.485 R149.1@18.6,58.4
MCU_GPIO0: R227.1 U6.12 | length 41.6
  L3 w0.12: v1(11,27.3) 11.6,27.9 11.6,31.9 10.9,32.6 10.9,34.012 10.315,34.597 10.315,35.159 11,35.844 v1(11,41.2)
  L8 w0.12: v1(11,27.3) 11,26.9 11.155,26.745 11.155,25.845 12.2,24.8 12.894,24.8 14.635,23.059 14.635,22.865 16.4,21.1 16.4,17.075 16.015,16.69 16.015,15.985 v1(18.6,13.4)
  L10 w0.114: R227.1@7.7,43.2 8.6,42.3 10.4,42.3 11,41.7 v1(11,41.2) ; v1(18.6,13.4) 18.9,13.4 19.4,13.9 19.4,16.044 18.925,16.519 U6.12@18.925,17.15
MCU_GPIO1: R228.1 U6.28 | length 21.2
  L3 w0.12: v1(8.3,32.9) 8.7,32.5 10.1,32.5 11,31.6 11,27.985 10.615,27.6 10.615,27.1 11.199,26.516 12.084,26.516 13.4,25.2 16.21,25.2 17.51,26.5 v1(18.3,26.5) ; v1@18.25,26.55 v1@18.3,26.6
  L10 w0.114: R228.1@7.6,33.1 8,33.1 8.1,33.1 v1(8.3,32.9) ; U6.28@18.275,23.85 18.275,24.281 17.365,25.191 17.365,25.559 17.415,25.609 17.415,25.615 v1(18.3,26.5)
MCU_GPIO2: R148.1 R205.2 R273.1 U6.9 | length 39.5
  L8 w0.12: v1(8.3,32) 8.6,32.3 10.2,32.3 10.86,31.64 10.86,28.06 10.5,27.7 10.5,26.8 10.82,26.48 10.82,25.48 11.815,24.485 12.484,24.485 13.806,23.163 13.806,22.8 14.106,22.5 14.4,22.5 15.9,21 15.9,17.4 15.7,17.2 15.7,15.5 18,13.2 18.256,13.2 v1@19.55,11.906 ; v1(19.55,11.85) v1@19.55,11.906 ; v1@19.6,11.856 v1@19.55,11.906
  L10 w0.114: R148.1@5.2,33.3 5.2,31.4 5.7,30.9 R205.2@6.2,30.9 R273.1@7.6,30.9 7.9,30.9 8.12,31.12 8.12,31.82 v1(8.3,32) ; v1(19.55,11.85) 19.55,12.15 20.875,13.475 U6.9@20.875,17.15
MCU_ISPN: R204.2 R213.1 U1.B21 | length 72.1
  L1 w0.114: v1(16.9,55.8) 16.9,55.5 17.275,55.125 17.875,55.125 17.963,55.037 19.163,55.037 19.7,54.5 20.8,54.5 U1.B21@21.2,54.9
  L8 w0.12: v1(16.9,55.8) 17.156,55.544 17.156,54.5 16.685,54.029 16.685,53.641 13.9,50.856 13.9,50.1 14.085,49.915 14.085,49.441 13.844,49.2 13.4,49.2 12.6,48.4 12.6,46.204 12.985,45.819 12.985,45.1 12.785,44.9 12.785,39.341 12.6,39.156 12.6,36.7 12.915,36.385 12.915,34.985 13.315,34.585 13.315,33.385 13.9,32.8 15,32.8 16.7,31.1 16.7,30.5 16.9,30.3 17.2,30.3 17.7,29.8 17.7,26.685 17.3,26.285 17.3,24.1 18.8,22.6 19.3,22.1 19.3,20.9 19.6,20.6 19.6,14.8 23.3,11.1 23.3,9.3 26.1,6.5 27.3,6.5 v1(27.8,6)
  L10 w0.114: R213.1@27.5,11.3 28.4,10.4 R204.2@28.6,10.4 28.6,9.2 28.1,8.7 28.1,6.3 v1(27.8,6)
MCU_RSTINN: R212.1 U1.A21 U21.1 U21.2 | length 54.2
  L1 w0.114: v1(16.2,56.2) 16.2,56.7 16.4,56.9 16.4,56.756 16.971,56.185 17.059,56.185 17.385,55.859 17.385,55.615 17.595,55.405 19.351,55.405 19.841,54.915 ; v1(17.3,28.6) 17.3,28.3 17.9,27.7 17.9,26.3 16.22,24.62 15.794,24.62 15.18,24.006 15.18,23.724 14.915,23.459 14.915,20.985 15.9,20 16.9,20 17.4,20.5 ; U21.2@17.95,20.6 17.5,20.6 17.4,20.5 ; U21.1@17.95,21.25 17.55,21.25 17.4,21.1 17.4,20.5 ; 19.841,54.915 19.856,54.9 U1.A21@20.4,54.9 20.4,54.915 19.841,54.915
  L8 w0.12: v1(16.2,56.2) 16.2,55.944 16.644,55.5 16.644,54.5 16.344,54.2 16.1,54.2 14.8,52.9 14.8,52.456 13.525,51.181 13.525,50.025 13.315,49.815 13.315,49.619 12.215,48.519 12.215,45.315 11.9,45 11.9,42.1 12.3,41.7 12.3,40.1 11.815,39.615 11.815,36.485 12.6,35.7 12.6,32.9 13.6,31.9 14.7,31.9 15.3,31.3 15.956,31.3 16.4,30.856 16.4,29.956 17.3,29.056 v1(17.3,28.6)
MCU_RSTINN_BUFF: R270.1 R281.1 U6.2 U21.4 | length 12
  L1 w0.114: R281.1@16.3,21.6 16.7,21.6 16.9,21.8 18.3,21.8 18.9,21.2 18.9,19.1 R270.1@19.2,18.8 19.85,19.45 U21.4@19.85,19.95 20.25,19.95 20.7,20.4 21.1,20.4 21.6,20.9 21.6,21.3 22.3,22 v1(22.9,22)
  L10 w0.114: U6.2@21.95,22.125 22.775,22.125 22.8,22.1 v1(22.9,22)
MCU_RSTOUTN: R93.1 U6.16 | length 36.9
  L8 w0.12: v1(11,43.8) 11,42 11.4,41.6 11.4,40.9 11,40.5 11,35.344 11.185,35.159 11.185,32.7 11.3,32.585 11.3,27.644 11.435,27.509 11.435,26.709 13.644,24.5 14.6,24.5 14.915,24.185 14.915,23.141 15.4,22.656 15.7,22.656 17.385,20.971 17.385,17.285 v1(16.4,16.3)
  L10 w0.114: v1(11,43.8) 11.735,44.535 12.465,44.535 14.1,42.9 R93.1@14.1,42.6 ; U6.16@16.325,17.15 16.325,16.375 v1(16.4,16.3)
MCU_RSTOUTN_R: R69.1 R93.2 R271.2 U8.2 | length 4.1
  L10 w0.114: U8.2@12.3,40.25 12.3,40.8 R69.1@12.9,41.4 13.015,41.515 15.5,41.515 R271.2@15.5,41.6
MCU_SWDIO: TP31.1 U1.P1 U25.3 | length 105.6
  L1 w0.114: v1(10.9,20.4) 11.42,20.92 11.42,22.72 U25.3@11.55,22.85 ; U1.P1@30.8,38.9 30.8,37 31,36.8 v1(31,36.3)
  L3 w0.12: v1(10.9,20.4) 11.756,20.4 12.541,19.615 13.115,19.615 13.28,19.78 14.66,19.78 15.7,18.74 15.7,17.3 15.3,16.9 15.3,15.964 17.865,13.399 17.865,12.491 18.365,11.991 18.365,11.791 18.63,11.526 18.87,11.526 18.929,11.585 19.259,11.585 19.6,11.244 19.6,10.8 22.485,7.915 22.641,7.915 23.456,7.1 25.2,7.1 25.5,6.8 28.1,6.8 29,5.9 29,5.656 30.456,4.2 33.9,4.2 34.4,3.7 36.9,3.7 37.1,3.5 40.5,3.5 43.2,3.5 43.7,4 47,4 47.8,4.8 48.344,4.8 48.6,5.056 48.6,5.9 49,6.3 49,7.1 49.5,7.6 49.5,8.31 50.758,9.568 50.758,10.458 51.531,11.231 51.531,12.831 54.333,15.633 54.333,17.333 54.7,17.7 54.7,18.2 53.9,19 49.8,19 48.4,20.4 47.1,20.4 46.4,21.1 v1(46.4,21.4)
  L8 w0.12: v1(31,36.3) 31.7,36.3 35.415,32.585 35.415,29.441 36.3,28.556 36.3,26.256 39.956,22.6 42.5,22.6 44.085,21.015 46.015,21.015 v1(46.4,21.4)
  L10 w0.114: TP31.1@30.2,36.1 30.8,36.1 v1(31,36.3)
MCU_SWDIO_SEL: R289.1 U1.N2 U25.6 | length 111.9
  L1 w0.114: v1(11.7,19.8) 12.3,20.4 12.3,20.515 R289.1@12.4,20.515 ; R289.1@12.4,20.6 12.8,20.6 14.635,22.435 14.635,23.575 14.9,23.84 14.9,24.2 14.615,24.485 13.985,24.485 13.65,24.15 U25.6@13.45,24.15 ; U1.N2@30,39.7 30.4,39.3 v1(30.4,36.8)
  L3 w0.12: v1(11.7,19.8) 12.165,19.335 13.4,19.335 13.565,19.5 14.385,19.5 15.285,18.6 15.285,17.5 14.9,17.115 14.9,15.9 17.585,13.215 17.585,12.375 18.085,11.875 18.085,11.671 22.256,7.5 22.66,7.5 23.46,6.7 25.019,6.7 25.319,6.4 28.104,6.4 28.585,5.919 28.585,5.675 30.46,3.8 32.415,3.8 32.8,3.415 34.25,3.415 34.515,3.15 44.95,3.15 45.3,3.5 47.644,3.5 49,4.856 49,5.7 49.9,6.6 49.9,8.1 51.115,9.315 51.115,10.159 51.877,10.921 51.877,12.677 54.767,15.567 54.767,17.167 55.2,17.6 55.2,18.5 54.3,19.4 50,19.4 48.7,20.7 47.356,20.7 46.815,21.241 46.815,21.585 46.6,21.8 46,21.8 v1(45.6,21.4)
  L8 w0.12: v1(30.4,36.8) 30.8,37.2 31.9,37.2 32.3,36.8 32.3,36.3 36.29,32.31 36.29,29.21 36.7,28.8 36.7,26.5 37.1,26.1 37.544,26.1 37.8,25.844 37.8,25.3 40.117,22.983 42.617,22.983 44.2,21.4 v1(45.6,21.4)
MCU_XTALIN: C223.2 U6.4 Y5.1 | length 6.3
  L10 w0.114: U6.4@21.95,20.825 22.769,20.825 23.5,20.094 C223.2@23.5,20 23.5,19.4 23.835,19.065 24.159,19.065 24.394,19.3 25.5,19.3 26.55,20.35 Y5.1@26.55,20.4
MCU_XTALOUT: C224.2 U6.5 Y5.3 | length 4.2
  L10 w0.114: U6.5@21.95,20.175 22.331,20.175 22.691,19.815 22.885,19.815 23.2,19.5 23.2,19.2 23.4,19 C224.2@23.4,18.7 23.715,18.385 24.85,18.385 Y5.3@24.85,18.2
MIC_BIAS: C293.1 R235.1 U14.16 | length 7.3
  L1 w0.3: v1(47.9,8.55) 48.8,7.65 50.95,7.65 51.3,7.3 52.06,7.3 52.08,7.28 v1(52.1,7.3)
  L10 w0.3: v1(47.9,8.55) U14.16@48.35,8.55 ; v1(52.1,7.3) 52.5,7.7 C293.1@52.8,7.7 53.5,7.7 R235.1@53.9,8.1
MIC_IN: C294.1 U14.15 | length 8.4
  L1 w0.3: v1(49.4,6.8) 49.407,6.793 52.3,6.793 52.7,7.193 52.7,7.396 53.194,7.89 54.39,7.89 v1(54.6,8.1)
  L10 w0.3: U14.15@48.85,8.55 48.85,8.103 49.4,7.553 v1(49.4,6.8) ; v1(54.6,8.1) C294.1@55.2,8.1
MIC_IN_C: C294.2 FB18.1 R235.2 | length 2.9
  L10 w0.3: R235.2@53.9,9.1 C294.2@55.2,9.1 55.3,9.1 56.3,8.1 FB18.1@56.4,8.1
MIC_LINEIN_L: TP7.1 U14.14 | length 1.6
  L10 w0.2: U14.14@49.35,8.55 49.35,8.183 50.1,7.433 TP7.1@50.1,7.3
MIC_LINEIN_R: TP41.1 U14.13 | length 1.9
  L10 w0.2: U14.13@49.85,8.55 49.85,8.192 50.142,7.9 50.5,7.9 51,7.4 TP41.1@51,7.3
MPCIE_SIM_C4: J17.C4 R104.1 | length 18.7
  L1 w0.114: R104.1@47.2,17.4 46.7,17.9 46.7,19.2 46.9,19.4 v1(47.3,19.4)
  L3 w0.12: v1(47.3,19.4) 47.152,19.4 45.952,20.6 45.445,20.6 44.9,21.145 44.9,23.5 46.1,24.7 46.1,25.9 46.785,26.585 47.87,26.585 48.355,26.1 v1(48.4,26.1)
  L10 w0.114: J17.C4@48.1,30.5 48,30.4 48,29.6 47.7,29.3 47.7,27.1 47.715,27.085 47.715,26.741 48.355,26.1 v1(48.4,26.1)
MPCIE_SIM_C4_R: J15.19 R104.2 | length 2.7
  L1 w0.114: R104.2@48.2,17.4 48.3,17.4 v1(48.9,16.8)
  L10 w0.114: J15.19@48.4,15.4 48.4,16.6 48.6,16.8 v1(48.9,16.8)
MPCIE_SIM_C8: J17.C8 R67.1 | length 15.4
  L1 w0.114: R67.1@48.2,18.6 R67.1@48.2,18.8 ; R67.1@48.2,18.7 v1(48.2,19.4)
  L3 w0.12: v1(47.4,26.2) 47.8,25.8 47.8,25.1 45.2,22.5 45.2,21.256 45.556,20.9 46.1,20.9 47,20 47.6,20 v1(48.2,19.4)
  L10 w0.114: J17.C8@46.83,30.5 46.885,30.445 46.885,26.715 v1(47.4,26.2)
MPCIE_SIM_C8_R: J15.17 R67.2 | length 4.9
  L1 w0.114: R67.2@47.2,18.7 47.2,18.5 47.6,18.1 v1(48.7,18.1)
  L10 w0.114: v1(48.7,18.1) 49.3,17.5 49.3,15.5 J15.17@49.2,15.4
MPCIE_SIM_CLK: D15.4 J15.12 J17.C3 | length 18.4
  L10 w0.114: J17.C3@50.64,30.5 50.64,29.84 50.3,29.5 49.5,29.5 49.3,29.3 49.3,28.3 49.5,28.1 49.9,28.1 50.1,27.9 50.1,27.7 50.4,27.4 51.034,27.4 51.2,27.234 51.2,26.5 50.7,26 D15.4@50.55,26 50.4,26 50.1,25.7 50.1,25.2 50.207,25.093 50.207,23.808 51.3,22.716 51.3,22.4 51.05,22.15 51.05,21.85 51.7,21.2 54.12,21.2 54.4,21.48 54.4,21.756 54.1,22.056 54.1,22.4 54.4,22.7 J15.12@54.4,23.6
MPCIE_SIM_DATA: D15.5 J15.10 J17.C7 | length 18.4
  L10 w0.114: J17.C7@49.37,30.5 49.37,30.37 48.5,29.5 48.5,28.3 48.7,28.1 49.044,28.1 49.3,27.844 49.3,27.556 49.556,27.3 50.06,27.3 50.36,27 D15.5@50.4,27 ; D15.5@50.55,27 D15.5@50.4,27 ; J15.10@55.2,23.6 55.2,22.7 54.9,22.4 54.9,21.5 54.2,20.8 51.5,20.8 50.5,21.8 50.5,22.8 49.8,23.5 49.8,26.4 D15.5@50.4,27
MPCIE_SIM_RST: D15.1 J15.14 J17.C2 | length 13.4
  L10 w0.114: J17.C2@53.18,30.5 53.18,29.98 52.5,29.3 52.5,27.488 D15.1@52.05,27.038 51.891,27.038 51.48,26.627 51.48,26.143 50.9,25.563 50.9,25 50.615,24.715 50.615,24.085 52.285,22.415 52.285,21.915 52.5,21.7 53.1,21.7 53.3,21.9 53.3,22.366 53.6,22.666 J15.14@53.6,23.6
NetC284_2: C284.2 R232.2 | length 1.1
  L10 w0.3: C284.2@63.5,8 63.5,8.4 63.7,8.6 R232.2@63.7,9
NetC285_2: C285.2 R233.2 | length 1.2
  L10 w0.3: C285.2@56.4,3.7 56.39,3.69 56.39,2.61 R233.2@56.5,2.5
NetC382_1: C382.1 D39.1 R141.1 R348.1 | length 8.1
  L10 w0.114: R348.1@1.4,31.1 2.4,31.1 2.6,30.9 2.6,30.4 2.3,30.1 R141.1@1.4,30.1 1.3,30.1 0.8,29.6 0.8,26.6 1.5,25.9 D39.1@1.5,25.719
NetC390_2: C390.2 R311.1 U22.3 | length 2.7
  L1 w0.3: U22.3@62.475,16.9 62.879,16.9 63.579,17.6 C390.2@63.6,17.6 63.6,18.7 R311.1@63.5,18.8
NetC411_1: C411.1 R344.2 | length 1.3
  L10 w0.4: C411.1@14.9,35.7 14.875,35.725 14.875,36.975 R344.2@14.9,37
NetC433_1: C433.1 R408.2 | length 1.1
  L10 w0.4: R408.2@10.5,93.8 C433.1@11.6,93.8
NetD11_1: D11.1 R267.2 | length 3.7
  L1 w0.114: R267.2@30.5,14.6 31.015,14.085 31.015,11.985 31.4,11.6 D11.1@31.4,11.3
NetD13_1: D13.1 R190.1 | length 1.3
  L1 w0.114: R190.1@40.7,76.6 40.7,75.419 D13.1@40.8,75.319
NetD14_1: D14.1 R185.1 | length 1.6
  L1 w0.114: R185.1@49.6,2.3 50,2.3 50.4,2.7 50.8,2.7 D14.1@51,2.7
NetD25_1: D25.1 R268.2 | length 4.6
  L1 w0.114: R268.2@29.5,13.2 29.5,13 30.7,11.8 30.7,10.1 D25.1@31.4,9.4
NetD26_1: D26.1 R269.2 | length 5
  L1 w0.114: R269.2@29.8,11.8 30.4,11.2 30.4,9.9 30.6,9.7 30.6,8.3 D26.1@31.4,7.5
NetJ5_14: J5.14 R182.1 | length 2.5
  L1 w0.3: J5.14@38.5,85.44 v1(38.5,87.1)
  L10 w0.4: R182.1@37.8,87.4 38.2,87.4 v1(38.5,87.1)
NetQ5_3: Q5.3 R186.2 | length 13.4
  L10 w0.114: R186.2@24.9,3.2 25.6,3.2 26.5,4.1 27.5,4.1 28.115,4.715 28.115,5.6 28.45,5.935 28.45,7.05 28.9,7.5 28.9,9.692 29.18,9.972 29.18,11.676 28.856,12 28.5,12 28.25,12.25 Q5.3@28.25,13.2
NetQ6_3: Q6.3 R185.2 | length 17.1
  L1 w0.114: R185.2@49.6,1.3 v1(50.2,1.3) ; v1(63,5.7) Q6.3@63,6.45 Q6.3@63.1,6.55
  L3 w0.12: v1(50.2,1.3) 51.2,1.3 51.9,2 55.8,2 56.3,2.5 56.3,4.1 57.9,5.7 v1(63,5.7)
NetQ10_1: Q10.1 R293.2 | length 1.5
  L10 w0.114: R293.2@15.7,1.2 16.2,1.2 16.35,1.35 Q10.1@17.1,1.35
NetQ14_3: Q14.3 R387.1 | length 4.8
  L10 w0.3: Q14.3@14.9,16.2 14.1,15.4 14.1,14.5 14.8,13.8 14.8,13.382 15.582,12.6 R387.1@15.8,12.6
NetR100_1: R100.1 R293.1 U27.1 | length 8.7
  L10 w0.3: R293.1@15.7,2.2 16.3,2.8 16.3,3.8 16.6,4.1 17.828,4.1 18.75,5.022 R100.1@18.75,5.2 18.75,6.75 20.05,8.05 U27.1@20.05,8.4
NetR109_2: R109.2 U15.7 | length 1.2
  L1 w0.114: R109.2@31.8,69.3 31.865,69.235 U15.7@31.865,68.15
NetR244_1: R244.1 U15.3 | length 3.4
  L1 w0.114: R244.1@32.3,59.8 32.6,59.8 32.9,60.1 32.9,61.5 33.135,61.735 U15.3@33.135,62.65
NetR292_1: R292.1 R296.2 U27.2 | length 5.8
  L10 w0.3: R292.1@20.2,9.7 20.21,9.69 20.71,9.69 U27.2@21.975,8.425 ; R296.2@21.3,5.2 21.417,5.2 21.95,5.733 U27.2@21.95,8.4
ON_OFF: R48.1 TP3.1 U1.D12 | length 12.7
  L1 w0.114: v1(22.4,47.3) U1.D12@22.8,47.7
  L3 w0.12: v1(13.6,44.2) 14.3,44.2 15.058,44.957 15.657,44.957 16.315,45.615 18.059,45.615 18.944,46.5 21.74,46.5 22.4,47.16 v1(22.4,47.3)
  L10 w0.114: R48.1@13.3,45.1 13.3,44.5 v1(13.6,44.2) 14.1,43.7 TP3.1@14.3,43.7
PCIE_C_TX_N: C63.1 U1.A3 | length 2.9
  L1 w0.114: C63.1@18.7,39.1 19.2,39.6 19.2,40.313 19.47,40.583 19.7,40.583 19.973,40.31 20.21,40.31 U1.A3@20.4,40.5
PCIE_C_TX_P: C65.1 U1.B3 | length 2.9
  L1 w0.114: C65.1@18.7,40.2 19.357,40.857 20.548,40.857 20.905,40.5 U1.B3@21.2,40.5
PCIE_CLK_C_N: C66.1 U1.C7 | length 9
  L1 w0.1: C66.1@17.7,37.9 17.7,38.22 17.9,38.42 v1(17.9,38.5) ; v1(21.6,43.3) U1.C7@22,43.7
  L3 w0.11: v1(17.9,38.5) 18,38.6 18,39.653 18.38,40.033 18.38,41.47 19.43,42.52 21.43,42.52 21.84,42.93 21.84,43.124 21.664,43.3 v1(21.6,43.3)
PCIE_CLK_C_P: C67.1 U1.D7 | length 9
  L1 w0.1: v1(18.5,38.5) 18.5,38.42 18.7,38.22 C67.1@18.7,37.9 ; v1(22.4,43.3) U1.D7@22.8,43.7
  L3 w0.11: v1(18.5,38.5) 18.32,38.68 18.32,39.52 18.7,39.9 18.7,41.337 19.563,42.2 21.563,42.2 22.16,42.797 22.16,43.06 v1(22.4,43.3)
PCIE_CLK_N: C66.2 J15.11 R17.2 | length 74.2
  L1 w0.1: C66.2@17.7,36.9 R17.2@17.7,35.8 17.9,35.6 v1(17.9,35.1)
  L3 w0.11: v1(17.9,35.1) 18.04,34.96 18.04,31.307 19.3,30.047 19.3,26.8 18.13,25.63 18.13,21.117 19,20.247 19,17.447 21.3,15.147 21.3,12.647 25.767,8.18 28.62,8.18 31.42,5.38 45.383,5.38 47.42,7.417 47.42,9.12 49.82,11.52 49.82,12.92 50.72,13.82 50.72,14.42 51.32,15.02 51.32,16.12 52.26,17.06 52.26,17.96 v1(52.4,18.1)
  L10 w0.1: v1(52.4,18.1) 52.26,17.96 52.26,17.74 52.505,17.495 54.158,17.495 54.56,17.093 54.56,16.69 54.8,16.45 J15.11@54.8,15.4
PCIE_CLK_P: C67.2 J15.13 R16.2 | length 74.2
  L1 w0.1: v1(18.5,35.1) 18.5,35.6 R16.2@18.7,35.8 C67.2@18.7,36.9
  L3 w0.11: v1(18.5,35.1) 18.36,34.96 18.36,31.44 19.62,30.18 19.62,26.667 18.45,25.497 18.45,21.25 19.32,20.38 19.32,17.58 21.62,15.28 21.62,12.78 25.9,8.5 28.753,8.5 31.553,5.7 45.25,5.7 47.1,7.55 47.1,9.253 47.724,9.876 47.724,10.1 47.45,10.374 47.45,10.65 47.65,10.85 47.926,10.85 48.2,10.576 48.424,10.576 49.5,11.653 49.5,13.053 50.4,13.953 50.4,14.553 51,15.153 51,16.253 51.94,17.193 51.94,17.96 v1(51.8,18.1)
  L10 w0.1: v1(51.8,18.1) 51.94,17.96 51.94,17.607 52.372,17.175 54.025,17.175 54.24,16.96 54.24,16.69 54,16.45 J15.13@54,15.4
PCIE_REXT: R37.2 U1.A2 | length 1.4
  L1 w0.4: v1(20,39.3) U1.A2@20.4,39.7
  L10 w0.4: v1(20,39.3) 20.1,39.4 R37.2@20.8,39.4
PCIE_RSTN: J15.22 R158.2 R170.1 | length 125.8
  L1 w0.114: v1(3.4,15.2) 3.8,15.6 3.8,18.4 4.085,18.685 4.085,19.159 3.8,19.444 3.8,20.256 5.5,21.956 5.5,22.936 6.6,24.036 6.6,24.4 7.35,25.15 7.35,26.17 7.12,26.4 7.12,28.02 7.3,28.2 7.3,29.9 7.157,30.043 7.157,33.443 6.4,34.2 6.4,35.8 6.8,36.2 6.8,36.9 7.2,37.3 10,37.3 v1(10.4,37.7) ; v1(48,22.2) R170.1@48,23.9
  L3 w0.12: v1(3.4,15.2) 2.8,14.6 2.8,12.8 5.7,9.9 5.7,9.356 8.685,6.371 8.685,4.559 8.985,4.259 8.985,3.815 10.465,2.335 12.665,2.335 13.185,1.815 13.559,1.815 13.844,2.1 17.3,2.1 19.4,4.2 21.7,4.2 22.1,3.8 23.3,3.8 23.7,3.4 29.672,3.4 30.572,2.5 33.475,2.5 33.875,2.1 47.756,2.1 48.741,3.085 49.585,3.085 51.2,4.7 51.2,6.2 51.8,6.8 52.144,6.8 52.8,7.456 52.8,8.9 52.915,9.015 52.915,12.409 53.3,12.794 53.935,12.794 54.455,13.315 55.015,13.315 56.5,14.8 56.5,19.6 55.2,20.9 50.6,20.9 49.7,21.8 48.4,21.8 v1(48,22.2)
  L10 w0.114: v1(10.4,37.7) 10.9,38.2 10.9,39.1 11.196,39.396 11.896,39.396 12.292,39 12.9,39 13.5,39.6 13.5,40.3 13.8,40.6 R158.2@14,40.6 ; R158.2@14.1,40.6 R158.2@14,40.6 ; R158.2@14.1,40.7 R158.2@14,40.6 ; J15.22@47.2,23.6 47.2,22.744 47.744,22.2 v1(48,22.2)
PCIE_RSTN_R: R170.2 U1.V5 | length 28.8
  L1 w0.114: U1.V5@34,42.1 34.4,41.7 35.8,41.7 36,41.5 36,41.1 36.2,40.9 36.6,40.9 36.815,40.685 36.815,37.941 37.015,37.741 37.015,35.485 37.985,34.515 37.985,32.985 v1(37.1,32.1) ; v1(46.8,25) 47,24.8 R170.2@47,23.9
  L10 w0.114: v1(37.1,32.1) 37.6,31.6 42.6,31.6 43.3,30.9 43.9,30.9 45.3,29.5 45.3,28.8 45.3,27.144 46.044,26.4 46.044,25.611 46.656,25 v1(46.8,25) v1@46.9,25
PCIE_RX_N: J15.23 U1.B1 | length 83.6
  L1 w0.114: v1(20.3,36.2) 20.242,36.258 20.242,36.555 20.674,36.987 20.674,37.274 20.8,37.4 21.04,37.4 21.19,37.55 21.19,37.85 21.04,38 20.8,38 20.674,38.126 20.674,38.491 21.083,38.9 U1.B1@21.2,38.9
  L3 w0.13: v1(20.3,36.2) 20.221,36.121 20.1,36.121 19.999,36.02 19.999,35.554 21.02,34.533 21.02,33.92 20.5,33.4 20.5,32.953 21.01,32.443 21.01,27.934 21.324,27.62 22.033,27.62 22.82,26.833 22.82,26.267 22.453,25.9 21,25.9 20.7,25.6 20.7,25 20.88,24.82 21.933,24.82 22.42,24.333 22.42,23.567 21.953,23.1 20.05,23.1 19.7,22.75 19.7,21.85 20.13,21.42 21.88,21.42 22.42,20.88 22.42,19.72 21.89,19.19 20.69,19.19 20.4,18.9 20.4,18.4 20.88,17.92 22.633,17.92 23.11,17.443 23.11,13.19 24.88,11.42 25.58,11.42 27.18,9.82 29.38,9.82 31.78,7.42 34.033,7.42 34.453,7 44.447,7 45.03,7.583 45.03,8.457 44.48,9.007 44.48,11.033 44.947,11.5 46.1,11.5 46.967,12.367 47.915,12.367 48.156,12.608 48.156,13.5 47.956,13.7 47.573,13.7 47.373,13.9 47.373,14.2 47.573,14.4 47.956,14.4 48.156,14.6 48.156,15.5 47.956,15.7 47.648,15.7 47.448,15.9 47.448,16.2 47.648,16.4 47.956,16.4 48.156,16.6 48.156,17.044 47.62,17.58 46.633,17.58 46.42,17.367 46.42,17.159 46.7,16.879 v1(46.7,16.8)
  L10 w0.114: v1(46.7,16.8) 46.7,16.59 46.8,16.49 J15.23@46.8,15.4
